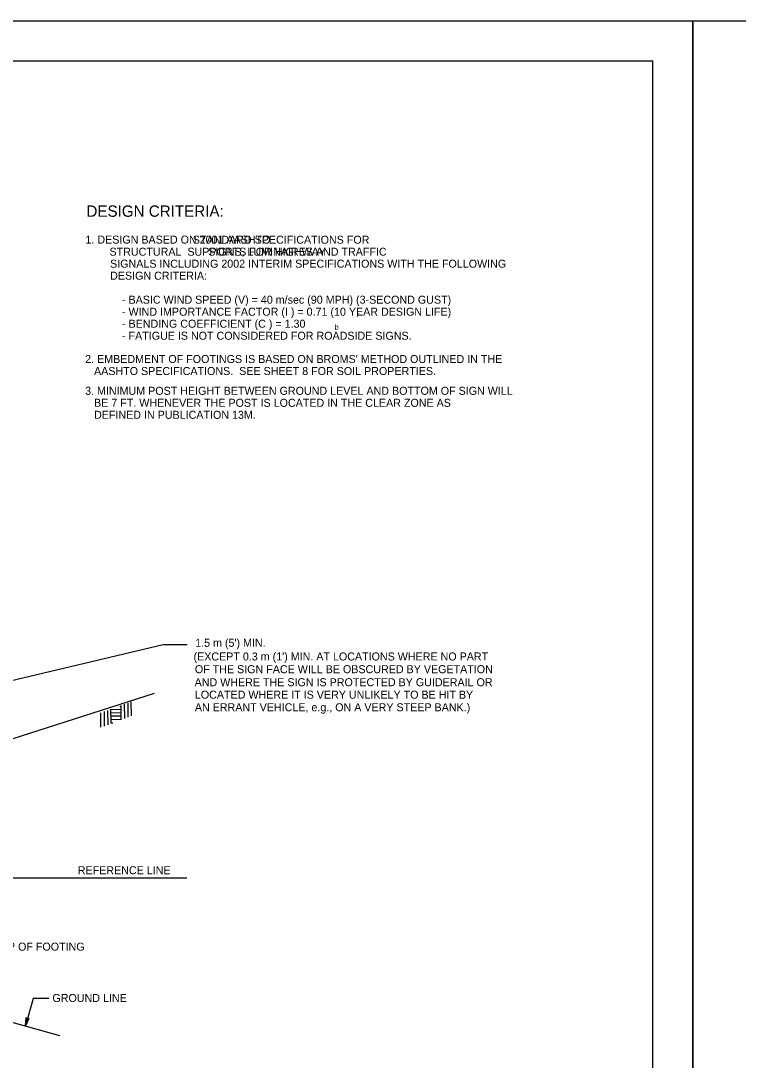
# Model space of a CAD drawing. Extents: x 637580 to 641008, y 294594 to 295782.
# Drawn here: x 638169.4 to 638438.3, y 295392.1 to 295781.6 of the extents above; entities that cross this region are included whole.
import ezdxf

# ---------------------------------------------------------------- set-up
doc = ezdxf.new("R2010")
doc.units = 0
for name, color, linetype in [('1', 7, 'Continuous'), ('2', 7, 'Continuous'), ('3', 7, 'Continuous'), ('PLT-BNDY', 7, 'Continuous')]:
    doc.layers.add(name, color=color, linetype=linetype)

# ---------------------------------------------------------------- blocks, each defined once
blk = doc.blocks.new('RARROW')
at = {"layer": '3'}
blk.add_lwpolyline([(-2.2695, 0.285), (-2.184875, 0.12075), (0, 0), (-2.2695, 0.285), (-2.38575, 0.384625), (0, 0), (-2.183125, -0.108), (-2.262875, -0.2705), (0, 0), (-2.38575, -0.379125), (-2.262875, -0.2705)], dxfattribs=at)

msp = doc.modelspace()

# ---------------------------------------------------------------- linework, layer by layer
at = {"layer": '1'}
for p, q in [((637620.31, 295766.63), (638406.31, 295766.63)), ((638406.31, 295202.63), (638406.31, 295766.63)), ((638148.69, 295530.25), (638222.81, 295547.88)), ((638210.94, 295521.13), (638210.81, 295526.38)), ((638199.44, 295516.88), (638199.44, 295522.25)), ((638200.81, 295517.25), (638200.81, 295522.75)), ((638202.19, 295517.75), (638202.06, 295523.13)), ((638203.19, 295523.5), (638207.06, 295523.63)), ((638203.31, 295518.38), (638203.19, 295523.63)), ((638203.31, 295522.25), (638207.19, 295522.38)), ((638206.56, 295524.75), (638207.06, 295524.75)), ((638207.06, 295519.75), (638207.06, 295525)), ((638208.44, 295520.13), (638208.31, 295525.5)), ((638209.69, 295520.63), (638209.69, 295525.88)), ((638203.31, 295521.13), (638207.06, 295521.13)), ((638203.31, 295519.75), (638207.19, 295519.88)), ((638203.31, 295518.5), (638203.94, 295518.5))]:
    msp.add_line(p, q, dxfattribs=at)
at = {"layer": '2'}
for p, q in [((638222.81, 295547.88), (638231.81, 295547.88)), ((638163.06, 295511.5), (638219.56, 295529.63)), ((637724.69, 295460.38), (638231.69, 295460.38)), ((637988.94, 295455.5), (638183.94, 295401.38)), ((638174.06, 295415.25), (638171.19, 295405)), ((638179.94, 295415.25), (638174.06, 295415.25))]:
    msp.add_line(p, q, dxfattribs=at)
at = {"layer": 'PLT-BNDY'}
for points in [[(637580.31, 295781.63), (638421.31, 295781.63), (638421.31, 295187.63), (637580.31, 295187.63)], [(638421.31, 295781.63), (639262.31, 295781.63), (639262.31, 295187.63), (638421.31, 295187.63)]]:
    msp.add_lwpolyline(points, close=True, dxfattribs=at)

# ---------------------------------------------------------------- block references
at = {"layer": '2', "xscale": 1.2574347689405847, "yscale": 1.3092961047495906, "rotation": -105.39526430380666}
msp.add_blockref('RARROW', (638171.19, 295405), dxfattribs=at)

# ---------------------------------------------------------------- texts
at = {"layer": '1'}
for s, height, p in [('1. DESIGN BASED ON 2001 AASHTO ', 3, (638193.69, 295698.12)), ('                            STANDARD SPECIFICATIONS FOR', 3, (638202.7, 295698.08)), ('STRUCTURAL  SUPPORTS FOR HIGHWAY ', 3, (638202.7, 295693.58)), ('                                 SIGNS, LUMINAIRES AND TRAFFIC', 3, (638202.92, 295693.59)), ('SIGNALS INCLUDING 2002 INTERIM SPECIFICATIONS WITH THE FOLLOWING', 3, (638202.92, 295689.09)), ('DESIGN CRITERIA:', 3, (638202.92, 295684.59)), ('    - BASIC WIND SPEED (V) = 40 m/sec (90 MPH) (3-SECOND GUST)', 3, (638202.92, 295675.59)), ('    - WIND IMPORTANCE FACTOR (I ) = 0.71 (10 YEAR DESIGN LIFE)', 3, (638202.92, 295671.09)), ('r', 2, (638295.45, 295670.57)), ('    - BENDING COEFFICIENT (C ) = 1.30', 3, (638202.92, 295666.59)), ('b', 2, (638287.06, 295665.79)), ('    - FATIGUE IS NOT CONSIDERED FOR ROADSIDE SIGNS.', 3, (638202.92, 295662.09)), ("2. EMBEDMENT OF FOOTINGS IS BASED ON BROMS' METHOD OUTLINED IN THE", 3, (638193.56, 295653.36)), ('   AASHTO SPECIFICATIONS.  SEE SHEET 8 FOR SOIL PROPERTIES.', 3, (638193.56, 295648.86)), ('3. MINIMUM POST HEIGHT BETWEEN GROUND LEVEL AND BOTTOM OF SIGN WILL', 3, (638193.56, 295641.45)), ('   BE 7 FT. WHENEVER THE POST IS LOCATED IN THE CLEAR ZONE AS', 3, (638193.56, 295636.95)), ('   DEFINED IN PUBLICATION 13M.', 3, (638193.56, 295632.45)), ("1.5 m (5') MIN.", 3, (638234.81, 295547)), ("(EXCEPT 0.3 m (1') MIN. AT LOCATIONS WHERE NO PART", 3, (638234.19, 295541.88)), ('OF THE SIGN FACE WILL BE OBSCURED BY VEGETATION', 3, (638234.69, 295537.11)), ('AND WHERE THE SIGN IS PROTECTED BY GUIDERAIL OR', 3, (638234.6, 295532.23)), ('LOCATED WHERE IT IS VERY UNLIKELY TO BE HIT BY', 3, (638234.69, 295527.56)), ('AN ERRANT VEHICLE, e.g., ON A VERY STEEP BANK.)', 3, (638234.68, 295522.84))]:
    msp.add_text(s, height=height, dxfattribs=at).set_placement(p)
at = {"layer": '2'}
msp.add_text('DESIGN CRITERIA:', height=4.25, dxfattribs=at).set_placement((638194.05, 295708.17))
at = {"layer": '3'}
for s, p in [('REFERENCE LINE', (638190.81, 295461.75)), ('TOP OF FOOTING', (638159.06, 295433.13)), ('GROUND LINE', (638181.31, 295413.88))]:
    msp.add_text(s, height=3, dxfattribs=at).set_placement(p)

doc.saveas('drawing.dxf')
